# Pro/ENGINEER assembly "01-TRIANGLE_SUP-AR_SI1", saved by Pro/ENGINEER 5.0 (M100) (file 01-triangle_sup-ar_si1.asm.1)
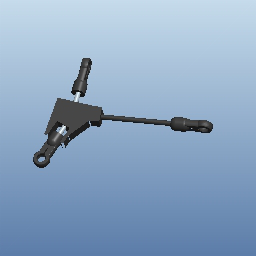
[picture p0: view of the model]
Units: millimeter Newton Second (mmNs); MM, TONNE, HOURS

Other components: 80127702-TRIANGLE_SUP-AR_SI1, T-5X30_SI1, T-5X30_SI1, 80022000-CHAPE_STD_COURTE_SI1, 80022000-CHAPE_STD_COURTE_SI1, 80022001-CHAPE_STD_DR_SI1

Other named items: 80127702-TRIANGLE_SUP-AR_01, 80022000-CHAPE_STD_COURTE_01, 80022001-CHAPE_STD_DR_01, T-5X30_01, A-DROITE, A-DESSUS, A-FACE, A-R0, ACS0, ACS1, ACS2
